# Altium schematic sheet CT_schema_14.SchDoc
size 144 x 119 mm
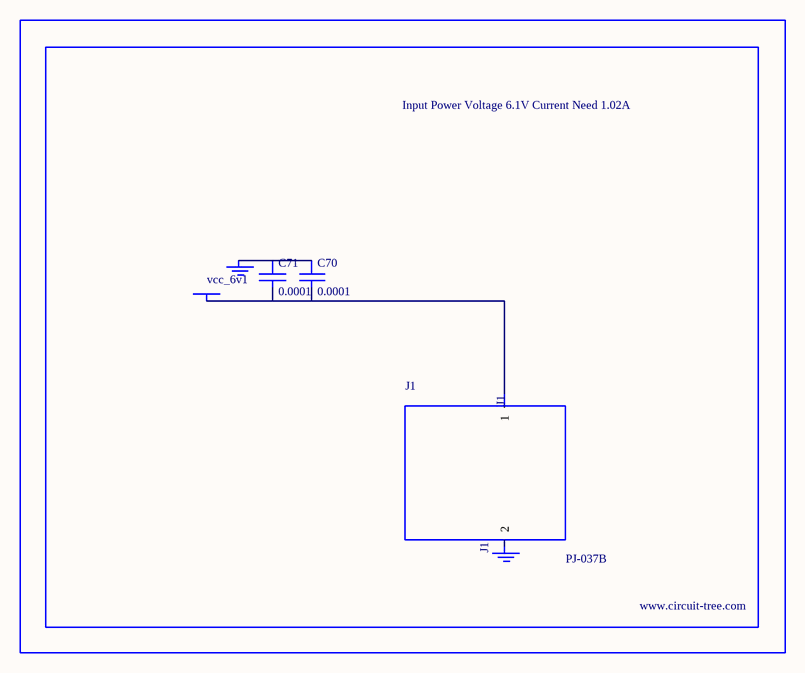
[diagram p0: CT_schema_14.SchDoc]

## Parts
BORDER13  (no value)
C70  0.0001  [EXV-9H]
C71  0.0001  [EXV-9H]
GND_INSTANCE_13_0  (no value)
GND_INSTANCE_13_1  (no value)
J1  PJ-037B  [PJ-037B_PACKAGE]
POWER_INSTANCE_13_0  vcc_6v1

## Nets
NetC70_1: C70.1 C71.1 GND_INSTANCE_13_0.0(GND)
NetC70_2: C70.2 C71.2 J1.1 POWER_INSTANCE_13_0.0(PWR)

Not connected (* = marked no-connect by the designer): GND_INSTANCE_13_1 0(GND); J1 2

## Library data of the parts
BORDER13 = BORDER_PAGE13
C70 C71 = EDK107M035A9HAA
GND_INSTANCE_13_0 GND_INSTANCE_13_1 = GND
POWER_INSTANCE_13_0 = PWR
